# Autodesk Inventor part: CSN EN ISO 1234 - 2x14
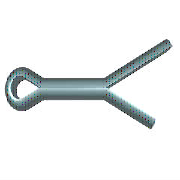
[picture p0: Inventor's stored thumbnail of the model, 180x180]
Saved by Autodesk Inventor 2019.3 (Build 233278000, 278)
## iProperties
Created: 2018-01
Part Number: CSN EN ISO 1234 - 2x14
Material: Ocel
Description: Závlačka
Document SubType Name: Modeling
Standard: CSN EN ISO 1234
Designer: B-hon
Standards Organization: CSN
Language: cs-CZ
Size Designation: 2x14
Categories: <MemberInstance><Categories><Category DisplayName="Spojovací materiál" InternalName="e4da775c-781d-43d5-af7c-5136215cf5a6" Mnemonic="FSTN"><Category DisplayName
Density: 7.85 g/cm^3
Sheet Metal Rule: Výchozí
Appearance: Plech
IsCustomPart: 0
Author: B-hon
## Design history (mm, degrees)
node "MSC_PF1"
node "MSC_A1"
node "MSC_PT1"
node "IDS_WORKPLANE{1}"
body "Solid1"
sketch "Náčrt1"
  geometry: L1 (4, 1)-(-4, 1); L2 (-4, 1)-(-5.476, 1.648); L3 (-5.476, -1.648)-(-4, -1); L4 (-4, -1)-(4, -1); L5 (4, -0.01)-(-4.208, -0.01); L6 (-4.208, -0.01)-(-5.874, -0.742); L7 (-5.874, 0.742)-(-4.208, 0.01); L8 (-4.208, 0.01)-(4, 0.01); L9 (9.011, 3.513)-(10, 4.01); L10 (10, 4.01)-(9.804, 2.921); L11 (12.89, -4.909)-(13, -6.01); L12 (12.053, -5.437)-(13, -6.01); L13 (-49.8, 0)-(53.8, 0) reference; L14 (4, 1)-(4, 0.01); L15 (4, -0.01)-(4, -1); L16 (-8, 0)-(-8, 15.609); L17 (-5.476, 1.648)-(-5.874, 0.742); L18 (9.011, 3.513)-(9.804, 2.921); L19 (9.408, 3.217)-(10, 4.01); L20 (12.89, -4.909)-(12.053, -5.437); L21 (12.471, -5.173)-(13, -6.01); L22 (-4, -1)-(4, 1); A1 r 1.8 centre (-6.2, 0) between (-5.476, 1.648) and (-5.476, -1.648); A2 r 0.81 centre (-6.2, 0) between (-5.874, 0.742) and (-5.874, -0.742); A3 r 6.253 centre (4, 7.253) between (4, 1) and (9.011, 3.513); A4 r 7.243 centre (4, 7.253) between (4, 0.01) and (9.804, 2.921); A5 r 10.515 centre (4, -10.525) between (12.89, -4.909) and (4, -0.01); A6 r 9.525 centre (4, -10.525) between (12.053, -5.437) and (4, -1); 3 further points
  constraints: 42 end point, 13 point on circle, 9 tangent, 6 centre point, 6 parallel, 5 equal length, 5 vertical alignment, 3 concentric, 3 midpoint, 3 perpendicular, 2 point on line, 1 collinear, 1 horizontal, 1 other
  dimensions: "d1" = 6 horizontal distance of L9.end A3.centre (= v); "d2" = 4 vertical distance of L9.end L8.end (= 0.666667 x d1); "d10" = 3.6 diameter of A1 (= ParC); "d11" = 2 distance between parallel lines of L4 L1 (= Diam); "d12" = 0.99 distance of L5.start L4.end (computed from d11); "d13" = 4 distance from line of L3.end L16 (= b); "d15" = 8 distance of L4.end L3.end (= prf_lf); "d16" = 6 distance from line of L5 L11.end (= 1.5 x d2); "d17" = 9 horizontal distance of L11.end A5.centre (= 1.5 x d1); "d26" = 0.99 distance of L2.end L7.start (= d12)
extrude "Vysunutí1" new body sketch "Náčrt1" stored distance "d18" = 2 (= Diam); taper "d19" = 0 deg
fillet "Zaoblení1" dims "d20" = 0.99 (= d12)
other parameters: "msp_Thickness" = 0.5, "msp_BendRadius" = 0.5 (= msp_Thickness), "msp_BendReliefWidth" = 0.5 (= msp_Thickness), "msp_BendReliefDepth" = 0.25 (= 0.5 x msp_Thickness), "msp_CornerReliefSize" = 2 (= 4 x msp_Thickness), "SeamGap" = 0.01, "msp_MinimumRemnant" = 1 (= 2 x msp_Thickness), "msp_TransitionRadius" = 0.5 (= msp_BendRadius), "b" = 4 [user parameter; used in 1 equation term], "ParC" = 3.6 [user parameter; used in 1 equation term], "Diam" = 2 [user parameter; used in 2 equation terms], "v" = 6 [user parameter; used in 1 equation term], "d27" = 0, "prf_lf" = 8 [user parameter; used in 1 equation term], "d32" = 0, "d33" = 0, "d34" = 0, "JacobiRadiusSize" = 0.5 (= msp_Thickness), "GapSize" = 0.5 (= msp_Thickness)
